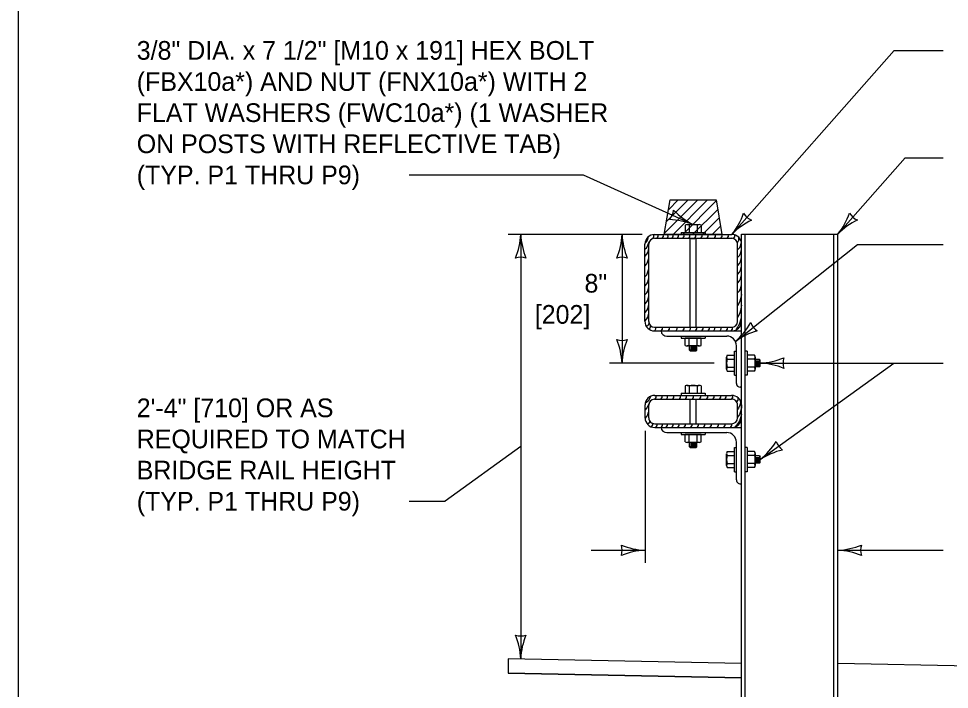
# Model space of a CAD drawing. Extents: x 49991.4 to 50021, y 49987.6 to 50011.4.
# Drawn here: x 49999.384 to 50002.376, y 49989.103 to 49991.258 of the extents above; entities that cross this region are included whole.
import ezdxf

# ---------------------------------------------------------------- set-up
doc = ezdxf.new("R2010")
doc.units = 0
for name, color, linetype in [('Level 1', 7, 'Continuous'), ('Level 2', 7, 'Continuous'), ('Level 3', 7, 'Continuous')]:
    doc.layers.add(name, color=color, linetype=linetype)

msp = doc.modelspace()

# ---------------------------------------------------------------- linework, layer by layer
at = {"layer": 'Level 1'}
for p, q in [((50001.4592, 49990.5643), (50001.4779, 49990.6754)), ((50001.4601, 49990.5682), (50001.5671, 49990.6754)), ((50001.4662, 49990.6058), (50001.5357, 49990.6754)), ((50001.4725, 49990.6435), (50001.5044, 49990.6754)), ((50001.4779, 49990.6754), (50001.626, 49990.6754)), ((50001.4875, 49990.5643), (50001.5987, 49990.6754)), ((50001.5188, 49990.5643), (50001.6265, 49990.6719)), ((50001.626, 49990.6754), (50001.6447, 49990.5643)), ((50001.5504, 49990.5643), (50001.6311, 49990.645)), ((50001.5819, 49990.5643), (50001.6356, 49990.6181)), ((50001.5263, 49990.5944), (50001.5263, 49990.5707)), ((50001.5327, 49990.596), (50001.571, 49990.596)), ((50001.539, 49990.5944), (50001.539, 49990.5708)), ((50001.5648, 49990.5944), (50001.5648, 49990.5708)), ((50001.5775, 49990.5944), (50001.5775, 49990.5707)), ((50001.6133, 49990.5643), (50001.64, 49990.5911)), ((50001.4281, 49990.5519), (50001.6764, 49990.5519)), ((50001.4282, 49990.5643), (50001.6768, 49990.5643)), ((50001.6447, 49990.5643), (50001.4592, 49990.5643)), ((50001.5132, 49990.5707), (50001.5908, 49990.5707)), ((50001.5132, 49990.5707), (50001.5132, 49990.5643)), ((50001.5263, 49990.5707), (50001.5775, 49990.5707)), ((50001.5424, 49990.2664), (50001.5424, 49990.5519)), ((50001.5458, 49990.5515), (50001.558, 49990.5515)), ((50001.562, 49990.2664), (50001.562, 49990.5519)), ((50001.5908, 49990.5707), (50001.5908, 49990.5643)), ((50001.7079, 49988.7839), (50001.7079, 49990.5649)), ((50001.7079, 49990.5649), (50002.0172, 49990.5649)), ((50001.7199, 49988.7839), (50001.7199, 49990.5649)), ((50002.005, 49988.7839), (50002.005, 49990.5649)), ((50002.0172, 49988.7839), (50002.0172, 49990.5649)), ((50001.397, 49990.2853), (50001.397, 49990.5335)), ((50001.4095, 49990.285), (50001.4095, 49990.5332)), ((50001.6948, 49990.2851), (50001.6948, 49990.5333)), ((50001.7079, 49990.285), (50001.7079, 49990.5332)), ((50001.7072, 49990.2853), (50001.7079, 49990.2975)), ((50001.428, 49990.2664), (50001.6762, 49990.2664)), ((50001.428, 49990.2543), (50001.7079, 49990.2543)), ((50001.4674, 49990.2378), (50001.6601, 49990.2378)), ((50001.5135, 49990.2375), (50001.5135, 49990.2317)), ((50001.5135, 49990.2317), (50001.5911, 49990.2317)), ((50001.5778, 49990.2317), (50001.5266, 49990.2317)), ((50001.5266, 49990.208), (50001.5266, 49990.2317)), ((50001.5393, 49990.208), (50001.5393, 49990.2316)), ((50001.5651, 49990.208), (50001.5651, 49990.2316)), ((50001.5778, 49990.208), (50001.5778, 49990.2317)), ((50001.5911, 49990.2375), (50001.5911, 49990.2317)), ((50001.5714, 49990.2064), (50001.5331, 49990.2064)), ((50001.5405, 49990.1925), (50001.5405, 49990.2064)), ((50001.5639, 49990.1925), (50001.5405, 49990.1925)), ((50001.5405, 49990.1925), (50001.5428, 49990.1902)), ((50001.5428, 49990.1902), (50001.5616, 49990.1902)), ((50001.5439, 49990.2031), (50001.5604, 49990.2031)), ((50001.5439, 49990.2008), (50001.5604, 49990.2008)), ((50001.5439, 49990.1984), (50001.5604, 49990.1984)), ((50001.5439, 49990.1961), (50001.5604, 49990.1961)), ((50001.5639, 49990.1925), (50001.5616, 49990.1902)), ((50001.5639, 49990.1925), (50001.5639, 49990.2064)), ((50001.6851, 49990.1122), (50001.6851, 49990.1898)), ((50001.6851, 49990.1898), (50001.6914, 49990.1898)), ((50001.6914, 49990.0859), (50001.6914, 49990.2072)), ((50001.7262, 49990.1898), (50001.7199, 49990.1898)), ((50001.7262, 49990.1898), (50001.7262, 49990.1122)), ((50001.6598, 49990.1318), (50001.6598, 49990.1701)), ((50001.6613, 49990.1639), (50001.685, 49990.1639)), ((50001.6614, 49990.1766), (50001.6851, 49990.1766)), ((50001.6851, 49990.1253), (50001.6851, 49990.1766)), ((50001.7262, 49990.1766), (50001.7262, 49990.1254)), ((50001.7499, 49990.1766), (50001.7262, 49990.1766)), ((50001.75, 49990.1639), (50001.7263, 49990.1639)), ((50001.7515, 49990.1702), (50001.7515, 49990.1319)), ((50001.7654, 49990.1627), (50001.7515, 49990.1627)), ((50001.7547, 49990.1427), (50001.7547, 49990.1592)), ((50001.7571, 49990.1427), (50001.7571, 49990.1592)), ((50001.7595, 49990.1427), (50001.7595, 49990.1592)), ((50001.7618, 49990.1427), (50001.7618, 49990.1592)), ((50001.7654, 49990.1627), (50001.7654, 49990.1393)), ((50001.7654, 49990.1627), (50001.7677, 49990.1604)), ((50001.7677, 49990.1416), (50001.7677, 49990.1604)), ((50001.6613, 49990.138), (50001.685, 49990.138)), ((50001.6614, 49990.1253), (50001.6851, 49990.1253)), ((50001.7499, 49990.1254), (50001.7262, 49990.1254)), ((50001.75, 49990.1381), (50001.7263, 49990.1381)), ((50001.7654, 49990.1393), (50001.7515, 49990.1393)), ((50001.7654, 49990.1393), (50001.7677, 49990.1416)), ((50001.6851, 49990.1122), (50001.6914, 49990.1122)), ((50001.7262, 49990.1122), (50001.7199, 49990.1122)), ((50001.5266, 49990.0779), (50001.5266, 49990.0542)), ((50001.533, 49990.0795), (50001.5713, 49990.0795)), ((50001.5393, 49990.0779), (50001.5393, 49990.0543)), ((50001.5651, 49990.0779), (50001.5651, 49990.0543)), ((50001.5778, 49990.0779), (50001.5778, 49990.0542)), ((50001.7079, 49990.0733), (50001.7036, 49990.0733)), ((50001.428, 49990.0475), (50001.6757, 49990.0475)), ((50001.428, 49990.0351), (50001.6757, 49990.0351)), ((50001.5135, 49990.0542), (50001.5911, 49990.0542)), ((50001.5135, 49990.0542), (50001.5135, 49990.0479)), ((50001.5266, 49990.0542), (50001.5778, 49990.0542)), ((50001.5424, 49989.9564), (50001.5424, 49990.0351)), ((50001.5461, 49990.0351), (50001.5584, 49990.0351)), ((50001.562, 49989.9564), (50001.562, 49990.0351)), ((50001.5911, 49990.0542), (50001.5911, 49990.0479)), ((50001.3975, 49989.9753), (50001.3975, 49990.0171)), ((50001.4095, 49989.9749), (50001.4095, 49990.0167)), ((50001.6948, 49989.9747), (50001.6948, 49990.0165)), ((50001.7072, 49990.0166), (50001.7079, 49990.0075)), ((50001.4285, 49989.9564), (50001.6762, 49989.9564)), ((50001.4285, 49989.9443), (50001.7079, 49989.9443)), ((50001.4674, 49989.928), (50001.6601, 49989.928)), ((50001.5135, 49989.9275), (50001.5135, 49989.9216)), ((50001.5135, 49989.9216), (50001.5911, 49989.9216)), ((50001.5778, 49989.9216), (50001.5266, 49989.9216)), ((50001.5266, 49989.8979), (50001.5266, 49989.9216)), ((50001.5393, 49989.8979), (50001.5393, 49989.9215)), ((50001.5651, 49989.8979), (50001.5651, 49989.9215)), ((50001.5778, 49989.8979), (50001.5778, 49989.9216)), ((50001.5911, 49989.9275), (50001.5911, 49989.9216)), ((50001.5714, 49989.8963), (50001.5331, 49989.8963)), ((50001.5405, 49989.8825), (50001.5405, 49989.8963)), ((50001.5439, 49989.8931), (50001.5604, 49989.8931)), ((50001.5439, 49989.8908), (50001.5604, 49989.8908)), ((50001.5439, 49989.8884), (50001.5604, 49989.8884)), ((50001.5439, 49989.8861), (50001.5604, 49989.8861)), ((50001.5639, 49989.8825), (50001.5639, 49989.8963)), ((50001.6914, 49989.7759), (50001.6914, 49989.8974)), ((50001.5639, 49989.8825), (50001.5405, 49989.8825)), ((50001.5405, 49989.8825), (50001.5428, 49989.8802)), ((50001.5428, 49989.8802), (50001.5616, 49989.8802)), ((50001.5639, 49989.8825), (50001.5616, 49989.8802)), ((50001.6598, 49989.8219), (50001.6598, 49989.8602)), ((50001.6614, 49989.8667), (50001.6851, 49989.8667)), ((50001.6851, 49989.8023), (50001.6851, 49989.8799)), ((50001.6851, 49989.8799), (50001.6914, 49989.8799)), ((50001.6851, 49989.8154), (50001.6851, 49989.8667)), ((50001.7262, 49989.8799), (50001.7199, 49989.8799)), ((50001.7262, 49989.8799), (50001.7262, 49989.8023)), ((50001.7262, 49989.8667), (50001.7262, 49989.8155)), ((50001.7499, 49989.8667), (50001.7262, 49989.8667)), ((50001.7515, 49989.8603), (50001.7515, 49989.822)), ((50001.6613, 49989.854), (50001.685, 49989.854)), ((50001.6613, 49989.8281), (50001.685, 49989.8281)), ((50001.75, 49989.854), (50001.7263, 49989.854)), ((50001.75, 49989.8282), (50001.7263, 49989.8282)), ((50001.7654, 49989.8528), (50001.7515, 49989.8528)), ((50001.7654, 49989.8294), (50001.7515, 49989.8294)), ((50001.7547, 49989.8328), (50001.7547, 49989.8493)), ((50001.7571, 49989.8328), (50001.7571, 49989.8493)), ((50001.7595, 49989.8328), (50001.7595, 49989.8493)), ((50001.7618, 49989.8328), (50001.7618, 49989.8493)), ((50001.7654, 49989.8528), (50001.7654, 49989.8294)), ((50001.7654, 49989.8528), (50001.7677, 49989.8505)), ((50001.7654, 49989.8294), (50001.7677, 49989.8317)), ((50001.7677, 49989.8317), (50001.7677, 49989.8505)), ((50001.6614, 49989.8154), (50001.6851, 49989.8154)), ((50001.6851, 49989.8023), (50001.6914, 49989.8023)), ((50001.7262, 49989.8023), (50001.7199, 49989.8023)), ((50001.7499, 49989.8155), (50001.7262, 49989.8155)), ((50001.7079, 49989.1865), (50000.9579, 49989.2015)), ((50001.7079, 49989.1397), (50001.7079, 49989.1865)), ((50002.7181, 49989.1725), (50002.0172, 49989.1865)), ((50000.9579, 49989.1547), (50001.7079, 49989.1397)), ((50001.7079, 49989.1397), (50000.9579, 49989.1547))]:
    msp.add_line(p, q, dxfattribs=at)
msp.add_lwpolyline([(49999.3835, 49998.9992), (50016.7501, 49998.9992), (50016.7501, 49987.7988), (49999.3835, 49987.7988)], close=True, dxfattribs=at)
for points in [[(50001.3972, 49990.5355), (50001.4031, 49990.542), (50001.4061, 49990.5479), (50001.409, 49990.5576)], [(50001.4188, 49990.5495), (50001.4238, 49990.5539), (50001.4258, 49990.5576), (50001.4258, 49990.5639)], [(50001.4367, 49990.5519), (50001.4402, 49990.5575), (50001.4402, 49990.5643)], [(50001.4526, 49990.5519), (50001.4566, 49990.5575), (50001.4554, 49990.5643)], [(50001.4684, 49990.5519), (50001.4719, 49990.557), (50001.4713, 49990.5643)], [(50001.4847, 49990.5519), (50001.4883, 49990.5575), (50001.4883, 49990.5643)], [(50001.5016, 49990.5519), (50001.5052, 49990.5575), (50001.5052, 49990.5643)], [(50001.519, 49990.5519), (50001.523, 49990.5575), (50001.5225, 49990.5643)], [(50001.5388, 49990.5519), (50001.5416, 49990.557), (50001.5416, 49990.5643)], [(50001.5576, 49990.5519), (50001.5612, 49990.5575), (50001.5612, 49990.5643)], [(50001.5773, 49990.5519), (50001.5808, 49990.5575), (50001.5808, 49990.5643)], [(50001.5974, 49990.5519), (50001.6008, 49990.5575), (50001.6002, 49990.5643)], [(50001.621, 49990.5519), (50001.6241, 49990.5575), (50001.6241, 49990.5643)], [(50001.6412, 49990.5519), (50001.6452, 49990.5575), (50001.6446, 49990.5643)], [(50001.6618, 49990.5519), (50001.6656, 49990.5575), (50001.6645, 49990.5643)], [(50001.682, 49990.5511), (50001.6861, 49990.557), (50001.6861, 49990.5632)], [(50001.6944, 49990.5378), (50001.6988, 49990.5459), (50001.6988, 49990.5552)], [(50001.3972, 49990.5176), (50001.4031, 49990.5226), (50001.4067, 49990.53), (50001.4109, 49990.541)], [(50001.3972, 49990.4935), (50001.4031, 49990.5011), (50001.4061, 49990.5068), (50001.4095, 49990.5178)], [(50001.695, 49990.5145), (50001.7019, 49990.5223), (50001.7045, 49990.5279), (50001.7079, 49990.5398)], [(50001.695, 49990.4899), (50001.7014, 49990.4968), (50001.7041, 49990.5031), (50001.7079, 49990.5155)], [(50001.3972, 49990.4629), (50001.4031, 49990.4695), (50001.4057, 49990.4751), (50001.4095, 49990.4878)], [(50001.695, 49990.4635), (50001.7014, 49990.4708), (50001.7041, 49990.4777), (50001.7079, 49990.49)], [(50001.695, 49990.4357), (50001.7014, 49990.4435), (50001.7041, 49990.4491), (50001.7079, 49990.4625)], [(50001.3972, 49990.4287), (50001.4031, 49990.435), (50001.4057, 49990.4408), (50001.4095, 49990.4535)], [(50001.3972, 49990.3985), (50001.4031, 49990.4055), (50001.4061, 49990.4112), (50001.4095, 49990.4246)], [(50001.695, 49990.4084), (50001.7014, 49990.4153), (50001.7041, 49990.4218), (50001.7079, 49990.4343)], [(50001.3972, 49990.37), (50001.4031, 49990.3764), (50001.4061, 49990.3827), (50001.4095, 49990.3963)], [(50001.695, 49990.3763), (50001.7014, 49990.3832), (50001.7041, 49990.3891), (50001.7079, 49990.4029)], [(50001.3972, 49990.3409), (50001.4031, 49990.3479), (50001.4061, 49990.3536), (50001.4095, 49990.367)], [(50001.7079, 49990.3712), (50001.7045, 49990.3573), (50001.7014, 49990.3467), (50001.695, 49990.335)], [(50001.3972, 49990.313), (50001.4031, 49990.3199), (50001.4061, 49990.3256), (50001.4095, 49990.339)], [(50001.7079, 49990.3369), (50001.7045, 49990.3199), (50001.7014, 49990.3092), (50001.695, 49990.2975)], [(50001.3972, 49990.2861), (50001.4031, 49990.2929), (50001.4061, 49990.2987), (50001.4095, 49990.3113)], [(50001.4095, 49990.28), (50001.4084, 49990.276), (50001.4061, 49990.2711), (50001.4012, 49990.2697)], [(50001.7057, 49990.294), (50001.7045, 49990.2891), (50001.7014, 49990.2779), (50001.6956, 49990.2675), (50001.6903, 49990.2611)], [(50001.4108, 49990.2595), (50001.4147, 49990.2664), (50001.4147, 49990.2721)], [(50001.4285, 49990.2543), (50001.432, 49990.2607), (50001.4316, 49990.2664)], [(50001.4496, 49990.2543), (50001.4532, 49990.2602), (50001.4532, 49990.2664)], [(50001.4722, 49990.2543), (50001.4763, 49990.2602), (50001.4763, 49990.2664)], [(50001.4976, 49990.2543), (50001.5008, 49990.2607), (50001.5008, 49990.2664)], [(50001.5188, 49990.2543), (50001.5229, 49990.2607), (50001.5223, 49990.2664)], [(50001.54, 49990.2543), (50001.544, 49990.2607), (50001.5429, 49990.2664)], [(50001.56, 49990.2543), (50001.5641, 49990.2607), (50001.5641, 49990.2664)], [(50001.5801, 49990.2543), (50001.5847, 49990.2607), (50001.5837, 49990.2664)], [(50001.6, 49990.2543), (50001.6044, 49990.2607), (50001.6037, 49990.2664)], [(50001.6186, 49990.2543), (50001.6221, 49990.2607), (50001.6221, 49990.2664)], [(50001.6391, 49990.2543), (50001.6428, 49990.2607), (50001.6428, 49990.2664)], [(50001.6585, 49990.2543), (50001.6629, 49990.2602), (50001.6629, 49990.2664)], [(50001.6749, 49990.2543), (50001.6787, 49990.2602), (50001.6787, 49990.2664)], [(50001.4147, 49990.0436), (50001.4115, 49990.0362), (50001.4072, 49990.0293), (50001.4036, 49990.0256), (50001.3978, 49990.0209)], [(50001.43, 49990.0351), (50001.4336, 49990.0409), (50001.4336, 49990.0463)], [(50001.4484, 49990.0351), (50001.4521, 49990.0409), (50001.4521, 49990.0463)], [(50001.4664, 49990.0347), (50001.47, 49990.0409), (50001.47, 49990.0463)], [(50001.4871, 49990.0351), (50001.4902, 49990.0409), (50001.4902, 49990.0463)], [(50001.5083, 49990.0351), (50001.5117, 49990.0409), (50001.5117, 49990.0463)], [(50001.5271, 49990.0351), (50001.5304, 49990.0409), (50001.5304, 49990.0463)], [(50001.5504, 49990.0351), (50001.5536, 49990.0409), (50001.5536, 49990.0463)], [(50001.574, 49990.0362), (50001.5774, 49990.0419), (50001.5774, 49990.0467)], [(50001.5952, 49990.0351), (50001.5995, 49990.0409), (50001.599, 49990.0463)], [(50001.6158, 49990.0351), (50001.6196, 49990.0409), (50001.6196, 49990.0463)], [(50001.6375, 49990.0362), (50001.6412, 49990.0419), (50001.6412, 49990.0467)], [(50001.6554, 49990.0362), (50001.6585, 49990.0419), (50001.6585, 49990.0467)], [(50001.6758, 49990.0351), (50001.6793, 49990.0409), (50001.6793, 49990.0467)], [(50001.6925, 49990.0266), (50001.6966, 49990.0323), (50001.6966, 49990.0388)], [(50001.4105, 49990.0219), (50001.4072, 49990.015), (50001.4036, 49990.0078), (50001.3972, 49990.0003)], [(50001.7052, 49990.0263), (50001.7019, 49990.0157), (50001.6978, 49990.0062), (50001.695, 49990.0019)], [(50001.7072, 49990.0071), (50001.7045, 49989.9955), (50001.7008, 49989.9855), (50001.695, 49989.9771)], [(50001.3976, 49989.9733), (50001.4031, 49989.9797), (50001.4061, 49989.9855), (50001.4084, 49989.9939)], [(50001.7079, 49989.9871), (50001.7045, 49989.9749), (50001.7008, 49989.9654), (50001.6956, 49989.9575)], [(50001.4122, 49989.9654), (50001.4115, 49989.9618), (50001.4088, 49989.957), (50001.4051, 49989.9554)], [(50001.4188, 49989.9464), (50001.4228, 49989.9523), (50001.4228, 49989.9572)], [(50001.4327, 49989.9443), (50001.4368, 49989.9502), (50001.4364, 49989.9559)], [(50001.45, 49989.9448), (50001.4537, 49989.9507), (50001.4537, 49989.9559)], [(50001.4657, 49989.9448), (50001.47, 49989.9507), (50001.47, 49989.9559)], [(50001.4844, 49989.9448), (50001.4881, 49989.9507), (50001.4881, 49989.9559)], [(50001.5034, 49989.9443), (50001.5072, 49989.9502), (50001.5065, 49989.9554)], [(50001.5233, 49989.9448), (50001.5271, 49989.9507), (50001.5271, 49989.9559)], [(50001.5452, 49989.9448), (50001.5488, 49989.9507), (50001.5482, 49989.9559)], [(50001.5658, 49989.9448), (50001.5699, 49989.9507), (50001.5693, 49989.9559)], [(50001.5863, 49989.9448), (50001.5895, 49989.9507), (50001.5895, 49989.9559)], [(50001.6068, 49989.9448), (50001.6111, 49989.9507), (50001.6105, 49989.9559)], [(50001.6303, 49989.9448), (50001.634, 49989.9507), (50001.634, 49989.9559)], [(50001.6506, 49989.9448), (50001.6551, 49989.9507), (50001.6544, 49989.9559)], [(50001.6728, 49989.9443), (50001.6762, 49989.9502), (50001.6762, 49989.9554)], [(50001.6956, 49989.9575), (50001.6871, 49989.9464)], [(50000.9579, 49989.2015), (50000.9579, 49989.1547)]]:
    msp.add_lwpolyline(points, dxfattribs=at)
for centre, radius, start, end in [((50001.4282, 49990.5332), 0.031, 90, 180), ((50001.4282, 49990.5333), 0.0186, 90, 180), ((50001.6762, 49990.5333), 0.0186, 0, 90), ((50001.6768, 49990.5333), 0.031, 0, 90), ((50001.428, 49990.2853), 0.031, 180, 270), ((50001.428, 49990.285), 0.0186, 180, 270), ((50001.6762, 49990.2853), 0.031, 270, 0), ((50001.6762, 49990.285), 0.0186, 270, 0), ((50001.4677, 49990.2568), 0.019, 187.4795, 269.7626), ((50001.6603, 49990.2069), 0.031, 0, 90), ((50001.7035, 49990.0858), 0.0124, 180, 270), ((50001.4283, 49990.0167), 0.0308, 89.6613, 179.6613), ((50001.428, 49990.0165), 0.0186, 90, 180), ((50001.6762, 49990.0165), 0.031, 0.198, 90.8862), ((50001.6762, 49990.0165), 0.0186, 0, 91.4754), ((50001.4285, 49989.9753), 0.031, 180, 270), ((50001.428, 49989.9749), 0.0185, 180.0701, 271.5094), ((50001.6762, 49989.975), 0.0186, 270.0634, 0.0634), ((50001.6768, 49989.9754), 0.031, 270, 0), ((50001.4673, 49989.9466), 0.0186, 187.1909, 270.2905), ((50001.6602, 49989.8968), 0.0312, 0.2444, 90.2444), ((50001.7038, 49989.7759), 0.0124, 180, 289.2595)]:
    msp.add_arc(centre, radius, start, end, dxfattribs=at)
for centre, major_axis, start_param, end_param in [((50001.5327, 49990.584), (0.0128, 0), 1.056847, 2.094396), ((50001.5519, 49990.548), (0.0512, 0), 1.315951, 1.825641), ((50001.5711, 49990.584), (0.0128, 0), 1.047198, 2.084746), ((50001.533, 49990.2184), (-0.0128, 0), 1.047198, 2.084746), ((50001.5522, 49990.2544), (-0.0512, 0), 1.315951, 1.825641), ((50001.5714, 49990.2184), (-0.0128, 0), 1.056847, 2.094396), ((50001.6718, 49990.1702), (0, 0.0128), 1.047198, 2.084746), ((50001.7077, 49990.151), (0, 0.0512), 1.315951, 1.825641), ((50001.7395, 49990.1702), (0, -0.0128), 1.056847, 2.094396), ((50001.7036, 49990.151), (0, -0.0512), 1.315951, 1.825641), ((50001.6718, 49990.1317), (0, 0.0128), 1.056847, 2.094396), ((50001.7395, 49990.1318), (0, -0.0128), 1.047198, 2.084746), ((50001.533, 49990.0675), (0.0128, 0), 1.056847, 2.094396), ((50001.5522, 49990.0315), (0.0512, 0), 1.315951, 1.825641), ((50001.5714, 49990.0675), (0.0128, 0), 1.047198, 2.084746), ((50001.533, 49989.9083), (-0.0128, 0), 1.047198, 2.084746), ((50001.5522, 49989.9443), (-0.0512, 0), 1.315951, 1.825641), ((50001.5714, 49989.9083), (-0.0128, 0), 1.056847, 2.094396), ((50001.6718, 49989.8603), (0, 0.0128), 1.047198, 2.084746), ((50001.7395, 49989.8603), (0, -0.0128), 1.056847, 2.094396), ((50001.6718, 49989.8218), (0, 0.0128), 1.056847, 2.094396), ((50001.7077, 49989.8411), (0, 0.0512), 1.315951, 1.825641), ((50001.7395, 49989.8219), (0, -0.0128), 1.047198, 2.084746), ((50001.7036, 49989.8411), (0, -0.0512), 1.315951, 1.825641)]:
    msp.add_ellipse(centre, major_axis=major_axis, ratio=0.93686, start_param=start_param, end_param=end_param, dxfattribs=at)
at = {"layer": 'Level 3'}
for p, q in [((50001.6768, 49990.5643), (50002.1986, 49991.1556)), ((50002.1986, 49991.1556), (50002.3559, 49991.1556)), ((50002.0172, 49990.5649), (50002.2341, 49990.8107)), ((50002.2341, 49990.8107), (50002.3559, 49990.8107)), ((50000.6388, 49990.7556), (50001.1984, 49990.7556)), ((50001.1984, 49990.7556), (50001.552, 49990.596)), ((50001.3882, 49990.5643), (50000.9579, 49990.5643)), ((50000.9979, 49990.5643), (50000.9979, 49989.2015)), ((50001.3235, 49990.5643), (50001.3235, 49990.1508)), ((50001.6881, 49990.2207), (50002.0805, 49990.5326)), ((50002.0805, 49990.5326), (50002.3559, 49990.5326)), ((50001.6198, 49990.1508), (50001.2835, 49990.1508)), ((50001.7677, 49990.151), (50002.3559, 49990.151)), ((50001.7677, 49989.8411), (50002.1974, 49990.151)), ((50001.3975, 49989.9332), (50001.3975, 49989.5099)), ((50000.9979, 49989.8829), (50000.7553, 49989.7074)), ((50000.6388, 49989.7074), (50000.7553, 49989.7074)), ((50001.224, 49989.5499), (50001.3975, 49989.5499)), ((50002.0172, 49989.5499), (50002.3559, 49989.5499))]:
    msp.add_line(p, q, dxfattribs=at)
for centre, radius, start, end in [((50001.4351, 49990.6487), 0.0548, 317.844, 353.5664), ((50001.6517, 49990.7947), 0.2223, 223.1612, 243.3447), ((50001.4667, 49990.3792), 0.233, 68.5325, 87.7824), ((50001.4947, 49990.7097), 0.233, 321.3987, 340.6485), ((50001.8373, 49990.4105), 0.2223, 116.0274, 136.2109), ((50001.7616, 49990.6604), 0.0548, 210.7102, 246.4326), ((50001.8351, 49990.7103), 0.233, 321.3987, 340.6485), ((50002.1777, 49990.4111), 0.2223, 116.0274, 136.2109), ((50002.102, 49990.661), 0.0548, 210.7102, 246.4326), ((50000.7758, 49990.5735), 0.2223, 337.456, 357.6395), ((50001.2306, 49990.5758), 0.233, 182.8273, 202.0772), ((50001.1014, 49990.5735), 0.2223, 337.456, 357.6395), ((50001.5562, 49990.5758), 0.233, 182.8273, 202.0772), ((50000.9979, 49990.4361), 0.0548, 72.1388, 107.8612), ((50001.3235, 49990.4361), 0.0548, 72.1388, 107.8612), ((50001.5343, 49990.3957), 0.233, 311.3041, 330.5539), ((50001.7885, 49990.3004), 0.0548, 200.6156, 236.3379), ((50001.8191, 49990.0411), 0.2223, 105.9328, 126.1163), ((50001.3235, 49990.279), 0.0548, 252.1388, 287.8612), ((50001.0908, 49990.1393), 0.233, 2.8273, 22.0772), ((50001.5456, 49990.1416), 0.2223, 157.456, 177.6395), ((50001.7562, 49990.3838), 0.233, 272.8273, 292.0772), ((50001.8959, 49990.151), 0.0548, 162.1388, 197.8612), ((50001.7585, 49989.9289), 0.2223, 67.456, 87.6395), ((50001.6222, 49990.0231), 0.233, 308.6339, 327.8837), ((50001.8717, 49989.9161), 0.0548, 197.9454, 233.6677), ((50001.8902, 49989.6556), 0.2223, 103.2626, 123.4461), ((50001.4066, 49989.7721), 0.2223, 247.456, 267.6395), ((50001.2693, 49989.5499), 0.0548, 342.1388, 17.8612), ((50002.0057, 49989.7827), 0.233, 272.8273, 292.0772), ((50002.1454, 49989.5499), 0.0548, 162.1388, 197.8612), ((50001.409, 49989.3172), 0.233, 92.8273, 112.0772), ((50002.008, 49989.3278), 0.2223, 67.456, 87.6395), ((50000.9979, 49989.3297), 0.0548, 252.1388, 287.8612), ((50000.7652, 49989.19), 0.233, 2.8273, 22.0772), ((50001.22, 49989.1924), 0.2223, 157.456, 177.6395)]:
    msp.add_arc(centre, radius, start, end, dxfattribs=at)

# ---------------------------------------------------------------- texts
at = {"layer": 'Level 2'}
for s, p in [('3/8" DIA. x 7 1/2" [M10 x 191] HEX BOLT', (49999.7633, 49991.1256)), ('(FBX10a*) AND NUT (FNX10a*) WITH 2 ', (49999.7633, 49991.0256)), ('FLAT WASHERS (FWC10a*) (1 WASHER ', (49999.7633, 49990.9256)), ('ON POSTS WITH REFLECTIVE TAB) ', (49999.7633, 49990.8256)), ('(TYP. P1 THRU P9)', (49999.7633, 49990.7256)), ('8"', (50001.2028, 49990.3776)), ('[202]', (50001.0431, 49990.2776)), ('2\'-4" [710] OR AS ', (49999.7633, 49989.9774)), ('REQUIRED TO MATCH ', (49999.7633, 49989.8774)), ('BRIDGE RAIL HEIGHT ', (49999.7633, 49989.7774)), ('(TYP. P1 THRU P9)', (49999.7633, 49989.6774))]:
    msp.add_text(s, height=0.06, dxfattribs=at).set_placement(p)

doc.saveas('drawing.dxf')
